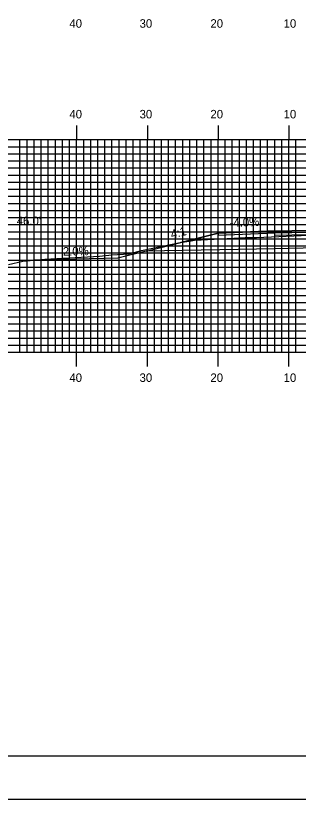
# Model space of a CAD drawing. Extents: x 1824360 to 1824703, y 442591 to 442811.
# Drawn here: x 1824476.7 to 1824516.7, y 442590.5 to 442701.2 of the extents above; entities that cross this region are included whole.
import ezdxf

# ---------------------------------------------------------------- set-up
doc = ezdxf.new("R2010")
doc.units = 0
for name, color, linetype in [('ANNOTATION', 7, 'Continuous'), ('BORDER', 7, 'Continuous'), ('D_Roadway_Centerline', 7, 'Continuous'), ('D_Roadway_Edge_Shoulder', 7, 'Continuous'), ('D_Roadway_Edge_TW', 7, 'Continuous'), ('D_Roadway_Pavement', 7, 'Continuous'), ('D_Roadway_SlopeLines', 7, 'Continuous'), ('D_Roadway_SubGrade', 7, 'Continuous'), ('D_Text_Standard', 7, 'Continuous'), ('H_V ANNOTATION', 7, 'Continuous'), ('MAJOR', 7, 'Continuous'), ('MINOR', 7, 'Continuous'), ('PLOT BOUNDARY', 7, 'Continuous'), ('S_Roadway_Centerline', 7, 'Continuous')]:
    doc.layers.add(name, color=color, linetype=linetype)

msp = doc.modelspace()

# ---------------------------------------------------------------- linework, layer by layer
at = {"layer": 'BORDER'}
msp.add_lwpolyline([(1824375.73, 442596.67), (1824695.73, 442596.67), (1824695.73, 442806.67), (1824375.73, 442806.67)], close=True, dxfattribs=at)
at = {"layer": 'D_Roadway_Centerline'}
msp.add_lwpolyline([(1824495.16, 442667.92), (1824500.07, 442669.15), (1824505.33, 442670.46), (1824513.33, 442670.78), (1824525.33, 442671.02), (1824537.33, 442670.78), (1824545.33, 442670.46), (1824555.51, 442667.92), (1824559.51, 442666.92), (1824562.47, 442668.4), (1824563.72, 442668.96), (1824564.97, 442669.4), (1824566.22, 442669.7), (1824567.47, 442669.88)], dxfattribs=at)
at = {"layer": 'D_Roadway_Edge_Shoulder'}
msp.add_lwpolyline([(1824513.33, 442670.78), (1824505.33, 442670.46), (1824505.33, 442670.21), (1824513.33, 442670.53)], close=True, dxfattribs=at)
at = {"layer": 'D_Roadway_Edge_TW'}
msp.add_lwpolyline([(1824513.33, 442670.53), (1824513.33, 442670.78), (1824525.33, 442671.02), (1824537.33, 442670.78), (1824537.33, 442670.53), (1824525.33, 442670.77)], close=True, dxfattribs=at)
at = {"layer": 'D_Roadway_Pavement'}
msp.add_lwpolyline([(1824513.33, 442670.12), (1824513.33, 442670.53), (1824525.33, 442670.77), (1824537.33, 442670.53), (1824537.33, 442670.12), (1824525.33, 442670.36)], close=True, dxfattribs=at)
at = {"layer": 'D_Roadway_SlopeLines'}
for p, q in [((1824491.16, 442666.92), (1824481.16, 442666.72)), ((1824495.16, 442667.92), (1824491.16, 442666.92)), ((1824481.16, 442666.72), (1824479.29, 442666.67))]:
    msp.add_line(p, q, dxfattribs=at)
msp.add_lwpolyline([(1824505.33, 442670.46), (1824500.07, 442669.15)], dxfattribs=at)
at = {"layer": 'D_Roadway_SubGrade'}
msp.add_lwpolyline([(1824513.33, 442668.28), (1824495.16, 442667.92), (1824505.33, 442670.46), (1824505.33, 442670.21), (1824513.33, 442670.53), (1824525.33, 442670.77), (1824537.33, 442670.53), (1824545.33, 442670.21), (1824545.33, 442670.46), (1824555.51, 442667.92), (1824537.33, 442668.28), (1824525.33, 442668.52)], close=True, dxfattribs=at)
at = {"layer": 'MAJOR'}
for p, q in [((1824485.33, 442685.67), (1824485.33, 442683.67)), ((1824495.33, 442685.67), (1824495.33, 442683.67)), ((1824505.33, 442685.67), (1824505.33, 442683.67)), ((1824515.33, 442685.67), (1824515.33, 442683.67)), ((1824385.33, 442683.67), (1824665.33, 442683.67)), ((1824385.33, 442683.67), (1824665.33, 442683.67)), ((1824485.33, 442653.67), (1824485.33, 442683.67)), ((1824495.33, 442653.67), (1824495.33, 442683.67)), ((1824505.33, 442653.67), (1824505.33, 442683.67)), ((1824515.33, 442653.67), (1824515.33, 442683.67)), ((1824385.33, 442678.67), (1824665.33, 442678.67)), ((1824385.33, 442673.67), (1824665.33, 442673.67)), ((1824385.33, 442668.67), (1824665.33, 442668.67)), ((1824385.33, 442663.67), (1824665.33, 442663.67)), ((1824385.33, 442658.67), (1824665.33, 442658.67)), ((1824385.33, 442653.67), (1824665.33, 442653.67)), ((1824385.33, 442653.67), (1824665.33, 442653.67)), ((1824485.33, 442651.66), (1824485.33, 442653.67)), ((1824495.33, 442651.66), (1824495.33, 442653.67)), ((1824505.33, 442651.66), (1824505.33, 442653.67)), ((1824515.33, 442651.66), (1824515.33, 442653.67))]:
    msp.add_line(p, q, dxfattribs=at)
at = {"layer": 'MINOR'}
for p, q in [((1824477.33, 442653.67), (1824477.33, 442683.67)), ((1824478.33, 442653.67), (1824478.33, 442683.67)), ((1824479.33, 442653.67), (1824479.33, 442683.67)), ((1824480.33, 442653.67), (1824480.33, 442683.67)), ((1824481.33, 442653.67), (1824481.33, 442683.67)), ((1824482.33, 442653.67), (1824482.33, 442683.67)), ((1824483.33, 442653.67), (1824483.33, 442683.67)), ((1824484.33, 442653.67), (1824484.33, 442683.67)), ((1824486.33, 442653.67), (1824486.33, 442683.67)), ((1824487.33, 442653.67), (1824487.33, 442683.67)), ((1824488.33, 442653.67), (1824488.33, 442683.67)), ((1824489.33, 442653.67), (1824489.33, 442683.67)), ((1824490.33, 442653.67), (1824490.33, 442683.67)), ((1824491.33, 442653.67), (1824491.33, 442683.67)), ((1824492.33, 442653.67), (1824492.33, 442683.67)), ((1824493.33, 442653.67), (1824493.33, 442683.67)), ((1824494.33, 442653.67), (1824494.33, 442683.67)), ((1824496.33, 442653.67), (1824496.33, 442683.67)), ((1824497.33, 442653.67), (1824497.33, 442683.67)), ((1824498.33, 442653.67), (1824498.33, 442683.67)), ((1824499.33, 442653.67), (1824499.33, 442683.67)), ((1824500.33, 442653.67), (1824500.33, 442683.67)), ((1824501.33, 442653.67), (1824501.33, 442683.67)), ((1824502.33, 442653.67), (1824502.33, 442683.67)), ((1824503.33, 442653.67), (1824503.33, 442683.67)), ((1824504.33, 442653.67), (1824504.33, 442683.67)), ((1824506.33, 442653.67), (1824506.33, 442683.67)), ((1824507.33, 442653.67), (1824507.33, 442683.67)), ((1824508.33, 442653.67), (1824508.33, 442683.67)), ((1824509.33, 442653.67), (1824509.33, 442683.67)), ((1824510.33, 442653.67), (1824510.33, 442683.67)), ((1824511.33, 442653.67), (1824511.33, 442683.67)), ((1824512.33, 442653.67), (1824512.33, 442683.67)), ((1824513.33, 442653.67), (1824513.33, 442683.67)), ((1824514.33, 442653.67), (1824514.33, 442683.67)), ((1824516.33, 442653.67), (1824516.33, 442683.67)), ((1824385.33, 442682.67), (1824665.33, 442682.67)), ((1824385.33, 442681.67), (1824665.33, 442681.67)), ((1824385.33, 442680.67), (1824665.33, 442680.67)), ((1824385.33, 442679.67), (1824665.33, 442679.67)), ((1824385.33, 442677.67), (1824665.33, 442677.67)), ((1824385.33, 442676.67), (1824665.33, 442676.67)), ((1824385.33, 442675.67), (1824665.33, 442675.67)), ((1824385.33, 442674.67), (1824665.33, 442674.67)), ((1824385.33, 442672.67), (1824665.33, 442672.67)), ((1824385.33, 442671.67), (1824665.33, 442671.67)), ((1824385.33, 442670.67), (1824665.33, 442670.67)), ((1824385.33, 442669.67), (1824665.33, 442669.67)), ((1824385.33, 442667.67), (1824665.33, 442667.67)), ((1824385.33, 442666.67), (1824665.33, 442666.67)), ((1824385.33, 442665.67), (1824665.33, 442665.67)), ((1824385.33, 442664.67), (1824665.33, 442664.67)), ((1824385.33, 442662.67), (1824665.33, 442662.67)), ((1824385.33, 442661.67), (1824665.33, 442661.67)), ((1824385.33, 442660.67), (1824665.33, 442660.67)), ((1824385.33, 442659.67), (1824665.33, 442659.67)), ((1824385.33, 442657.67), (1824665.33, 442657.67)), ((1824385.33, 442656.67), (1824665.33, 442656.67)), ((1824385.33, 442655.67), (1824665.33, 442655.67)), ((1824385.33, 442654.67), (1824665.33, 442654.67))]:
    msp.add_line(p, q, dxfattribs=at)
at = {"layer": 'PLOT BOUNDARY'}
msp.add_lwpolyline([(1824359.55, 442590.55), (1824699.55, 442590.55), (1824699.55, 442810.55), (1824359.55, 442810.55)], close=True, dxfattribs=at)
at = {"layer": 'S_Roadway_Centerline'}
msp.add_lwpolyline([(1824475.71, 442666.05), (1824477.74, 442666.54), (1824480.83, 442666.79), (1824488.57, 442667.23), (1824490.3, 442667.41), (1824492.75, 442667.56), (1824494.49, 442668), (1824499.96, 442669.13), (1824501.51, 442669.39), (1824502.01, 442669.48), (1824507.56, 442669.76), (1824509.14, 442669.84), (1824509.89, 442669.88), (1824510.76, 442669.86), (1824519.18, 442670.25)], dxfattribs=at)

# ---------------------------------------------------------------- texts
at = {"layer": 'ANNOTATION'}
for s, rotation, p in [('-4.0%', 2.2906, (1824506.97, 442671.33)), ('4:1', 14.0362, (1824498.78, 442669.69)), ('2.0%', 1.1458, (1824483.4, 442667.29))]:
    msp.add_text(s, height=1.2, rotation=rotation, dxfattribs=at).set_placement(p)
at = {"layer": 'D_Text_Standard'}
msp.add_text("46.0'", height=1.2, dxfattribs=at).set_placement((1824476.87, 442671.61))
at = {"layer": 'H_V ANNOTATION'}
for s, p in [('40', (1824484.31, 442699.47)), ('30', (1824494.23, 442699.47)), ('20', (1824504.24, 442699.47)), ('10', (1824514.59, 442699.47)), ('40', (1824484.31, 442686.67)), ('30', (1824494.23, 442686.67)), ('20', (1824504.24, 442686.67)), ('10', (1824514.59, 442686.67)), ('40', (1824484.31, 442649.47)), ('30', (1824494.23, 442649.47)), ('20', (1824504.24, 442649.47)), ('10', (1824514.59, 442649.47))]:
    msp.add_text(s, height=1.2, dxfattribs=at).set_placement(p)

doc.saveas('drawing.dxf')
